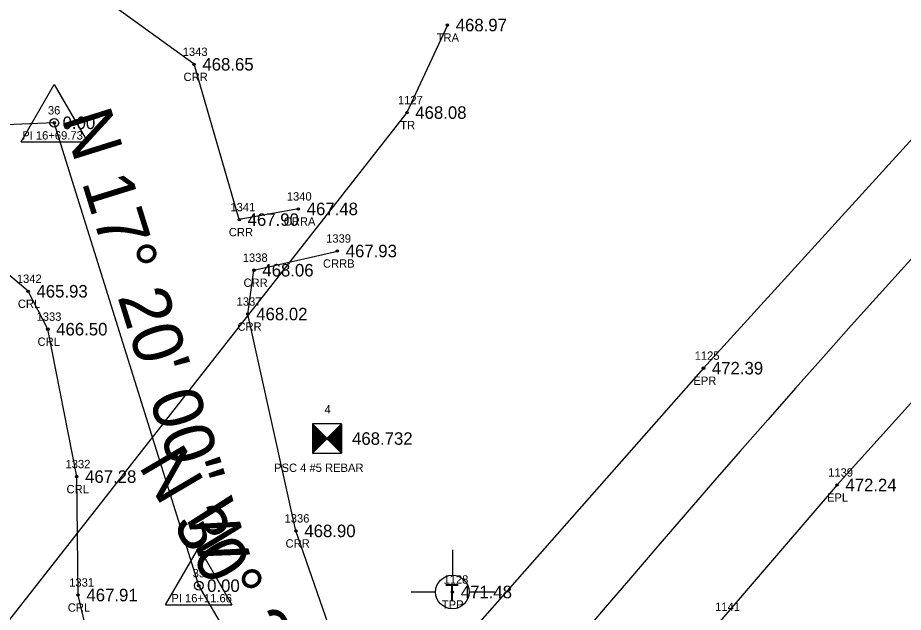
# Model space of a CAD drawing. Extents: x 1740701 to 1743138, y 748181 to 751839.
# Drawn here: x 1741552.9 to 1741658.9, y 750093.3 to 750164.5 of the extents above; entities that cross this region are included whole.
import ezdxf

# ---------------------------------------------------------------- set-up
doc = ezdxf.new("R2010")
doc.units = 0
for name, color, linetype in [('RD_EX_H2O', 7, 'Continuous'), ('RD_EX_H2O_txCode', 7, 'Continuous'), ('RD_EX_Road', 7, 'Continuous'), ('RD_EX_Road_txCode', 7, 'Continuous'), ('RD_EX_TX_H2O_ELEV', 7, 'Continuous'), ('RD_EX_TX_Road_ELEV', 7, 'Continuous'), ('RD_EX_TX_UT_ELEV', 7, 'Continuous'), ('RD_EX_TX_VEG_ELEV', 7, 'Continuous'), ('RD_EX_UT', 7, 'Continuous'), ('RD_EX_UT_txCode', 7, 'Continuous'), ('RD_EX_VEG', 7, 'Continuous'), ('RD_EX_VEG_txCode', 7, 'Continuous'), ('RD_HC_Cl', 7, 'Continuous'), ('RD_HC_Data', 7, 'Continuous'), ('RD_HC_Survey', 7, 'Continuous'), ('RD_HC_Survey_ELEV', 7, 'Continuous'), ('RD_HC_txCode', 7, 'Continuous'), ('RD_SMD_Locator', 7, 'Continuous')]:
    doc.layers.add(name, color=color, linetype=linetype)

msp = doc.modelspace()

# ---------------------------------------------------------------- linework, layer by layer
at = {"layer": 'RD_EX_H2O'}
for points in [[(1741586.49, 750141.56), (1741579.42, 750140.28), (1741574, 750158.88), (1741556.82, 750171.34), (1741542.92, 750162.75), (1741531.4, 750163.48), (1741496.74, 750161.28), (1741466.68, 750164.86), (1741447.36, 750172.02), (1741386.3, 750192.01)], [(1741577.19, 750059.87), (1741574.31, 750069.19), (1741563.25, 750082.19), (1741560.12, 750095.32), (1741559.96, 750109.5), (1741556.5, 750127.16), (1741554.14, 750131.7), (1741543.79, 750140.45), (1741537.22, 750131.72), (1741525.85, 750130.27), (1741518.7, 750134.1), (1741490.89, 750135.06), (1741436.94, 750142.19), (1741375.71, 750163.12), (1741339.37, 750188.79), (1741331.64, 750190.2), (1741328.64, 750186.11), (1741320.24, 750158.32), (1741318.27, 750146.83), (1741309.48, 750135.97), (1741304.66, 750127.91)], [(1741597.3, 750084.84), (1741591, 750089.11), (1741586.21, 750103), (1741580.45, 750128.97), (1741581.18, 750134.22), (1741591.16, 750136.52)]]:
    msp.add_lwpolyline(points, dxfattribs=at)
at = {"layer": 'RD_EX_Road'}
for points in [[(1742095.24, 750593.27), (1742088.27, 750587.97), (1742078.23, 750580.89), (1742049.13, 750555.21), (1742012.94, 750522.73), (1741975.54, 750488.03), (1741940.71, 750452.82), (1741916.22, 750428.67), (1741904.72, 750416.99), (1741884.38, 750395.02), (1741870.75, 750380.27), (1741817.36, 750322.98), (1741803.89, 750307.66), (1741783.86, 750287.33), (1741735.44, 750234.07), (1741718.84, 750214.98), (1741710.25, 750205.58), (1741668.97, 750159.8), (1741635, 750122.49), (1741604.35, 750087.7), (1741600.63, 750085.47)], [(1742102.43, 750570.61), (1742093.26, 750562.71), (1742064.72, 750538.42), (1742027.92, 750505.65), (1741991.25, 750471.83), (1741956.32, 750436.98), (1741921.43, 750401.39), (1741886.79, 750364.93), (1741819.64, 750292.67), (1741751.78, 750219.01), (1741684.42, 750145.59), (1741650.98, 750108.5), (1741637.17, 750092.42), (1741621.17, 750073.94), (1741621.31, 750072.22), (1741619.24, 750070.27)]]:
    msp.add_lwpolyline(points, dxfattribs=at)
at = {"layer": 'RD_EX_UT'}
for p, q in [((1741604.93, 750100.75), (1741604.93, 750097.68)), ((1741600, 750095.7), (1741602.93, 750095.7)), ((1741606.93, 750095.7), (1741610, 750095.7))]:
    msp.add_line(p, q, dxfattribs=at)
msp.add_circle((1741604.93, 750095.68), 2, dxfattribs=at)
at = {"layer": 'RD_EX_VEG'}
msp.add_lwpolyline([(1741604.33, 750163.58), (1741599.49, 750153.1), (1741534.68, 750070.43), (1741507.94, 750028.75), (1741481.7, 749984.37), (1741451.24, 749945.89), (1741428.74, 749900.3), (1741397.03, 749864.21), (1741369.46, 749820.4), (1741343.59, 749775.26), (1741290.16, 749691.55)], dxfattribs=at)
at = {"layer": 'RD_HC_Cl'}
for p, q in [((1741557.27, 750151.87), (1741493.93, 750149.37)), ((1741574.57, 750096.44), (1741557.27, 750151.87)), ((1741588.03, 750073.58), (1741574.57, 750096.44))]:
    msp.add_line(p, q, dxfattribs=at)
msp.add_arc((1743076.32, 748855.91), 1908.9, 137.32219, 146.96645, dxfattribs=at)
at = {"layer": 'RD_HC_Data'}
for p, q in [((1741553.3, 750149.58), (1741557.27, 750156.45)), ((1741557.27, 750156.45), (1741561.24, 750149.58)), ((1741553.3, 750149.58), (1741561.24, 750149.58)), ((1741570.6, 750094.14), (1741574.57, 750101.02)), ((1741574.57, 750101.02), (1741578.54, 750094.14)), ((1741570.6, 750094.14), (1741578.54, 750094.14))]:
    msp.add_line(p, q, dxfattribs=at)
for centre in [(1741557.27, 750151.87), (1741574.57, 750096.44)]:
    msp.add_circle(centre, 0.529, dxfattribs=at)
at = {"layer": 'RD_HC_Survey'}
for p, q in [((1741588.17, 750115.81), (1741591.67, 750112.31)), ((1741591.67, 750115.81), (1741588.17, 750112.31)), ((1741588.19, 750115.78), (1741588.19, 750112.33)), ((1741588.21, 750115.76), (1741588.21, 750112.36)), ((1741588.24, 750115.73), (1741588.24, 750112.38)), ((1741588.26, 750115.71), (1741588.26, 750112.41)), ((1741588.29, 750115.68), (1741588.29, 750112.43)), ((1741588.31, 750115.66), (1741588.31, 750112.46)), ((1741588.34, 750115.63), (1741588.34, 750112.48)), ((1741588.36, 750115.61), (1741588.36, 750112.5)), ((1741588.39, 750115.58), (1741588.39, 750112.53)), ((1741588.41, 750115.56), (1741588.41, 750112.55)), ((1741588.44, 750115.53), (1741588.44, 750112.58)), ((1741588.46, 750115.51), (1741588.46, 750112.6)), ((1741588.49, 750115.48), (1741588.49, 750112.63)), ((1741588.51, 750115.46), (1741588.51, 750112.65)), ((1741588.54, 750115.44), (1741588.54, 750112.68)), ((1741588.56, 750115.41), (1741588.56, 750112.7)), ((1741588.59, 750115.39), (1741588.59, 750112.73)), ((1741588.61, 750115.36), (1741588.61, 750112.75)), ((1741588.64, 750115.34), (1741588.64, 750112.78)), ((1741588.66, 750115.31), (1741588.66, 750112.8)), ((1741588.69, 750115.29), (1741588.69, 750112.83)), ((1741588.71, 750115.26), (1741588.71, 750112.85)), ((1741588.73, 750115.24), (1741588.73, 750112.88)), ((1741588.76, 750115.21), (1741588.76, 750112.9)), ((1741588.78, 750115.19), (1741588.78, 750112.93)), ((1741588.81, 750115.16), (1741588.81, 750112.95)), ((1741588.83, 750115.14), (1741588.83, 750112.97)), ((1741588.86, 750115.11), (1741588.86, 750113)), ((1741588.88, 750115.09), (1741588.88, 750113.02)), ((1741588.91, 750115.06), (1741588.91, 750113.05)), ((1741588.93, 750115.04), (1741588.93, 750113.07)), ((1741588.96, 750115.01), (1741588.96, 750113.1)), ((1741588.98, 750114.99), (1741588.98, 750113.12)), ((1741589.01, 750114.97), (1741589.01, 750113.15)), ((1741589.03, 750114.94), (1741589.03, 750113.17)), ((1741590.8, 750114.94), (1741590.8, 750113.17)), ((1741590.82, 750114.97), (1741590.82, 750113.15)), ((1741590.85, 750114.99), (1741590.85, 750113.12)), ((1741590.87, 750115.01), (1741590.87, 750113.1)), ((1741590.9, 750115.04), (1741590.9, 750113.07)), ((1741590.92, 750115.06), (1741590.92, 750113.05)), ((1741590.95, 750115.09), (1741590.95, 750113.02)), ((1741590.97, 750115.11), (1741590.97, 750113)), ((1741591, 750115.14), (1741591, 750112.97)), ((1741591.02, 750115.16), (1741591.02, 750112.95)), ((1741591.05, 750115.19), (1741591.05, 750112.93)), ((1741591.07, 750115.21), (1741591.07, 750112.9)), ((1741591.1, 750115.24), (1741591.1, 750112.88)), ((1741591.12, 750115.26), (1741591.12, 750112.85)), ((1741591.15, 750115.29), (1741591.15, 750112.83)), ((1741591.17, 750115.31), (1741591.17, 750112.8)), ((1741591.2, 750115.34), (1741591.2, 750112.78)), ((1741591.22, 750115.36), (1741591.22, 750112.75)), ((1741591.24, 750115.39), (1741591.24, 750112.73)), ((1741591.27, 750115.41), (1741591.27, 750112.7)), ((1741591.29, 750115.44), (1741591.29, 750112.68)), ((1741591.32, 750115.46), (1741591.32, 750112.65)), ((1741591.34, 750115.48), (1741591.34, 750112.63)), ((1741591.37, 750115.51), (1741591.37, 750112.6)), ((1741591.39, 750115.53), (1741591.39, 750112.58)), ((1741591.42, 750115.56), (1741591.42, 750112.55)), ((1741591.44, 750115.58), (1741591.44, 750112.53)), ((1741591.47, 750115.61), (1741591.47, 750112.5)), ((1741591.49, 750115.63), (1741591.49, 750112.48)), ((1741591.52, 750115.66), (1741591.52, 750112.46)), ((1741591.54, 750115.68), (1741591.54, 750112.43)), ((1741591.57, 750115.71), (1741591.57, 750112.41)), ((1741591.59, 750115.73), (1741591.59, 750112.38)), ((1741591.62, 750115.76), (1741591.62, 750112.36)), ((1741591.64, 750115.78), (1741591.64, 750112.33)), ((1741589.06, 750114.92), (1741589.06, 750113.2)), ((1741589.08, 750114.89), (1741589.08, 750113.22)), ((1741589.11, 750114.87), (1741589.11, 750113.25)), ((1741589.13, 750114.84), (1741589.13, 750113.27)), ((1741589.16, 750114.82), (1741589.16, 750113.3)), ((1741589.18, 750114.79), (1741589.18, 750113.32)), ((1741589.2, 750114.77), (1741589.2, 750113.35)), ((1741589.23, 750114.74), (1741589.23, 750113.37)), ((1741589.25, 750114.72), (1741589.25, 750113.4)), ((1741589.28, 750114.69), (1741589.28, 750113.42)), ((1741589.3, 750114.67), (1741589.3, 750113.45)), ((1741589.33, 750114.64), (1741589.33, 750113.47)), ((1741589.35, 750114.62), (1741589.35, 750113.49)), ((1741589.38, 750114.59), (1741589.38, 750113.52)), ((1741589.4, 750114.57), (1741589.4, 750113.54)), ((1741589.43, 750114.54), (1741589.43, 750113.57)), ((1741589.45, 750114.52), (1741589.45, 750113.59)), ((1741589.48, 750114.49), (1741589.48, 750113.62)), ((1741589.5, 750114.47), (1741589.5, 750113.64)), ((1741589.53, 750114.45), (1741589.53, 750113.67)), ((1741589.55, 750114.42), (1741589.55, 750113.69)), ((1741589.58, 750114.4), (1741589.58, 750113.72)), ((1741589.6, 750114.37), (1741589.6, 750113.74)), ((1741589.63, 750114.35), (1741589.63, 750113.77)), ((1741589.65, 750114.32), (1741589.65, 750113.79)), ((1741589.67, 750114.3), (1741589.67, 750113.82)), ((1741589.7, 750114.27), (1741589.7, 750113.84)), ((1741589.72, 750114.25), (1741589.72, 750113.87)), ((1741589.75, 750114.22), (1741589.75, 750113.89)), ((1741589.77, 750114.2), (1741589.77, 750113.92)), ((1741589.8, 750114.17), (1741589.8, 750113.94)), ((1741589.82, 750114.15), (1741589.82, 750113.96)), ((1741589.85, 750114.12), (1741589.85, 750113.99)), ((1741589.87, 750114.1), (1741589.87, 750114.01)), ((1741589.9, 750114.07), (1741589.9, 750114.04)), ((1741589.93, 750114.07), (1741589.93, 750114.04)), ((1741589.96, 750114.1), (1741589.96, 750114.01)), ((1741589.98, 750114.12), (1741589.98, 750113.99)), ((1741590.01, 750114.15), (1741590.01, 750113.96)), ((1741590.03, 750114.17), (1741590.03, 750113.94)), ((1741590.06, 750114.2), (1741590.06, 750113.92)), ((1741590.08, 750114.22), (1741590.08, 750113.89)), ((1741590.11, 750114.25), (1741590.11, 750113.87)), ((1741590.13, 750114.27), (1741590.13, 750113.84)), ((1741590.16, 750114.3), (1741590.16, 750113.82)), ((1741590.18, 750114.32), (1741590.18, 750113.79)), ((1741590.21, 750114.35), (1741590.21, 750113.77)), ((1741590.23, 750114.37), (1741590.23, 750113.74)), ((1741590.25, 750114.4), (1741590.25, 750113.72)), ((1741590.28, 750114.42), (1741590.28, 750113.69)), ((1741590.3, 750114.45), (1741590.3, 750113.67)), ((1741590.33, 750114.47), (1741590.33, 750113.64)), ((1741590.35, 750114.49), (1741590.35, 750113.62)), ((1741590.38, 750114.52), (1741590.38, 750113.59)), ((1741590.4, 750114.54), (1741590.4, 750113.57)), ((1741590.43, 750114.57), (1741590.43, 750113.54)), ((1741590.45, 750114.59), (1741590.45, 750113.52)), ((1741590.48, 750114.62), (1741590.48, 750113.49)), ((1741590.5, 750114.64), (1741590.5, 750113.47)), ((1741590.53, 750114.67), (1741590.53, 750113.45)), ((1741590.55, 750114.69), (1741590.55, 750113.42)), ((1741590.58, 750114.72), (1741590.58, 750113.4)), ((1741590.6, 750114.74), (1741590.6, 750113.37)), ((1741590.63, 750114.77), (1741590.63, 750113.35)), ((1741590.65, 750114.79), (1741590.65, 750113.32)), ((1741590.68, 750114.82), (1741590.68, 750113.3)), ((1741590.7, 750114.84), (1741590.7, 750113.27)), ((1741590.72, 750114.87), (1741590.72, 750113.25)), ((1741590.75, 750114.89), (1741590.75, 750113.22)), ((1741590.77, 750114.92), (1741590.77, 750113.2))]:
    msp.add_line(p, q, dxfattribs=at)
msp.add_lwpolyline([(1741591.67, 750115.81), (1741588.17, 750115.81), (1741588.17, 750112.31), (1741591.67, 750112.31)], close=True, dxfattribs=at)
at = {"layer": 'RD_SMD_Locator'}
for centre in [(1741604.33, 750163.58), (1741574, 750158.88), (1741599.49, 750153.1), (1741557.27, 750151.87), (1741586.49, 750141.56), (1741579.42, 750140.28), (1741591.16, 750136.52), (1741581.18, 750134.22), (1741554.14, 750131.7), (1741580.45, 750128.97), (1741556.5, 750127.16), (1741635, 750122.49), (1741589.92, 750114.06), (1741559.96, 750109.5), (1741650.98, 750108.5), (1741586.21, 750103), (1741574.57, 750096.44), (1741560.12, 750095.32), (1741604.93, 750095.68)]:
    msp.add_circle(centre, 0.15, dxfattribs=at)

# ---------------------------------------------------------------- texts
at = {"layer": 'RD_EX_H2O_txCode'}
for s, p in [('1343', (1741572.65, 750159.88)), ('CRR', (1741572.75, 750156.88)), ('1340', (1741585.11, 750142.56)), ('1341', (1741578.36, 750141.28)), ('CRRA', (1741584.75, 750139.56)), ('CRR', (1741578.17, 750138.28)), ('1339', (1741589.82, 750137.52)), ('1338', (1741579.84, 750135.22)), ('CRRB', (1741589.44, 750134.52)), ('1342', (1741552.79, 750132.7)), ('CRR', (1741579.93, 750132.22)), ('1337', (1741579.1, 750129.97)), ('CRL', (1741552.91, 750129.7)), ('1333', (1741555.15, 750128.16)), ('CRR', (1741579.2, 750126.97)), ('CRL', (1741555.27, 750125.16)), ('1332', (1741558.62, 750110.5)), ('CRL', (1741558.74, 750107.5)), ('1336', (1741584.84, 750104)), ('CRR', (1741584.96, 750101)), ('1331', (1741559.06, 750096.32)), ('CRL', (1741558.89, 750093.32))]:
    msp.add_text(s, height=1, dxfattribs=at).set_placement(p)
at = {"layer": 'RD_EX_Road_txCode'}
for s, p in [('1125', (1741633.94, 750123.49)), ('EPR', (1741633.78, 750120.49)), ('1139', (1741649.92, 750109.5)), ('EPL', (1741649.78, 750106.5)), ('1141', (1741636.39, 750093.42))]:
    msp.add_text(s, height=1, dxfattribs=at).set_placement(p)
at = {"layer": 'RD_EX_TX_H2O_ELEV'}
for s, p in [('468.65', (1741575, 750158.13)), ('467.48', (1741587.49, 750140.81)), ('467.90', (1741580.42, 750139.53)), ('467.93', (1741592.16, 750135.77)), ('468.06', (1741582.18, 750133.47)), ('465.93', (1741555.14, 750130.95)), ('468.02', (1741581.45, 750128.22)), ('466.50', (1741557.5, 750126.41)), ('467.28', (1741560.96, 750108.75)), ('468.90', (1741587.21, 750102.25)), ('467.91', (1741561.12, 750094.57))]:
    msp.add_text(s, height=1.5, dxfattribs=at).set_placement(p)
at = {"layer": 'RD_EX_TX_Road_ELEV'}
for s, p in [('472.39', (1741636, 750121.74)), ('472.24', (1741651.98, 750107.75))]:
    msp.add_text(s, height=1.5, dxfattribs=at).set_placement(p)
at = {"layer": 'RD_EX_TX_UT_ELEV'}
msp.add_text('471.48', height=1.5, dxfattribs=at).set_placement((1741605.93, 750094.93))
at = {"layer": 'RD_EX_TX_VEG_ELEV'}
for s, p in [('468.97', (1741605.33, 750162.83)), ('468.08', (1741600.49, 750152.35))]:
    msp.add_text(s, height=1.5, dxfattribs=at).set_placement(p)
at = {"layer": 'RD_EX_UT'}
msp.add_text('T', height=2, dxfattribs=at).set_placement((1741604.08, 750094.63))
at = {"layer": 'RD_EX_UT_txCode'}
for s, p in [('1128', (1741603.87, 750096.68)), ('TPP', (1741603.67, 750093.68))]:
    msp.add_text(s, height=1, dxfattribs=at).set_placement(p)
at = {"layer": 'RD_EX_VEG_txCode'}
for s, p in [('TRA', (1741603.05, 750161.58)), ('1127', (1741598.42, 750154.1)), ('TR', (1741598.69, 750151.1))]:
    msp.add_text(s, height=1, dxfattribs=at).set_placement(p)
at = {"layer": 'RD_HC_Data'}
for s, rotation, p in [('N 17%%d 20\' 00" W', 287.3334, (1741558.14, 750152.44)), ('N 30%%d 29\' 09" W', 300.4857, (1741567.28, 750110.79))]:
    msp.add_text(s, height=6, rotation=rotation, dxfattribs=at).set_placement(p)
at = {"layer": 'RD_HC_Survey_ELEV'}
for s, p in [('0.00', (1741558.27, 750151.12)), ('468.732', (1741592.92, 750113.31)), ('0.00', (1741575.57, 750095.69))]:
    msp.add_text(s, height=1.5, dxfattribs=at).set_placement(p)
at = {"layer": 'RD_HC_txCode'}
for s, p in [('36', (1741556.51, 750152.87)), ('PI 16+69.73', (1741553.44, 750149.87)), ('4', (1741589.63, 750117.06)), ('PSC 4 #5 REBAR', (1741583.59, 750110.06)), ('35', (1741573.84, 750097.44)), ('PI 16+11.66', (1741571.29, 750094.44))]:
    msp.add_text(s, height=1, dxfattribs=at).set_placement(p)

doc.saveas('drawing.dxf')
